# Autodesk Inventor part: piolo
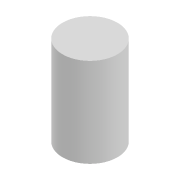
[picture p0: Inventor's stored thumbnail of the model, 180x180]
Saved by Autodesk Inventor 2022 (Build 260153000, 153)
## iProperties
Created: 2022-04
Part Number: piolo
Material: Generico
Document SubType Name: Modeling
Designer: i911900
Density: 1 g/cm^3
Appearance: Default
Author: i911900
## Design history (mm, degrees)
sketch "Schizzo1"
  geometry: C1 r 4 at (0, 0); 1 further point
  constraints: 1 centre point, 1 coincident
  dimensions: "d0" = 8 diameter of C1
extrude "Estrusione1" new body sketch "Schizzo1" distance "d1" = 13; taper "d2" = 0 deg
node "Solido1"
